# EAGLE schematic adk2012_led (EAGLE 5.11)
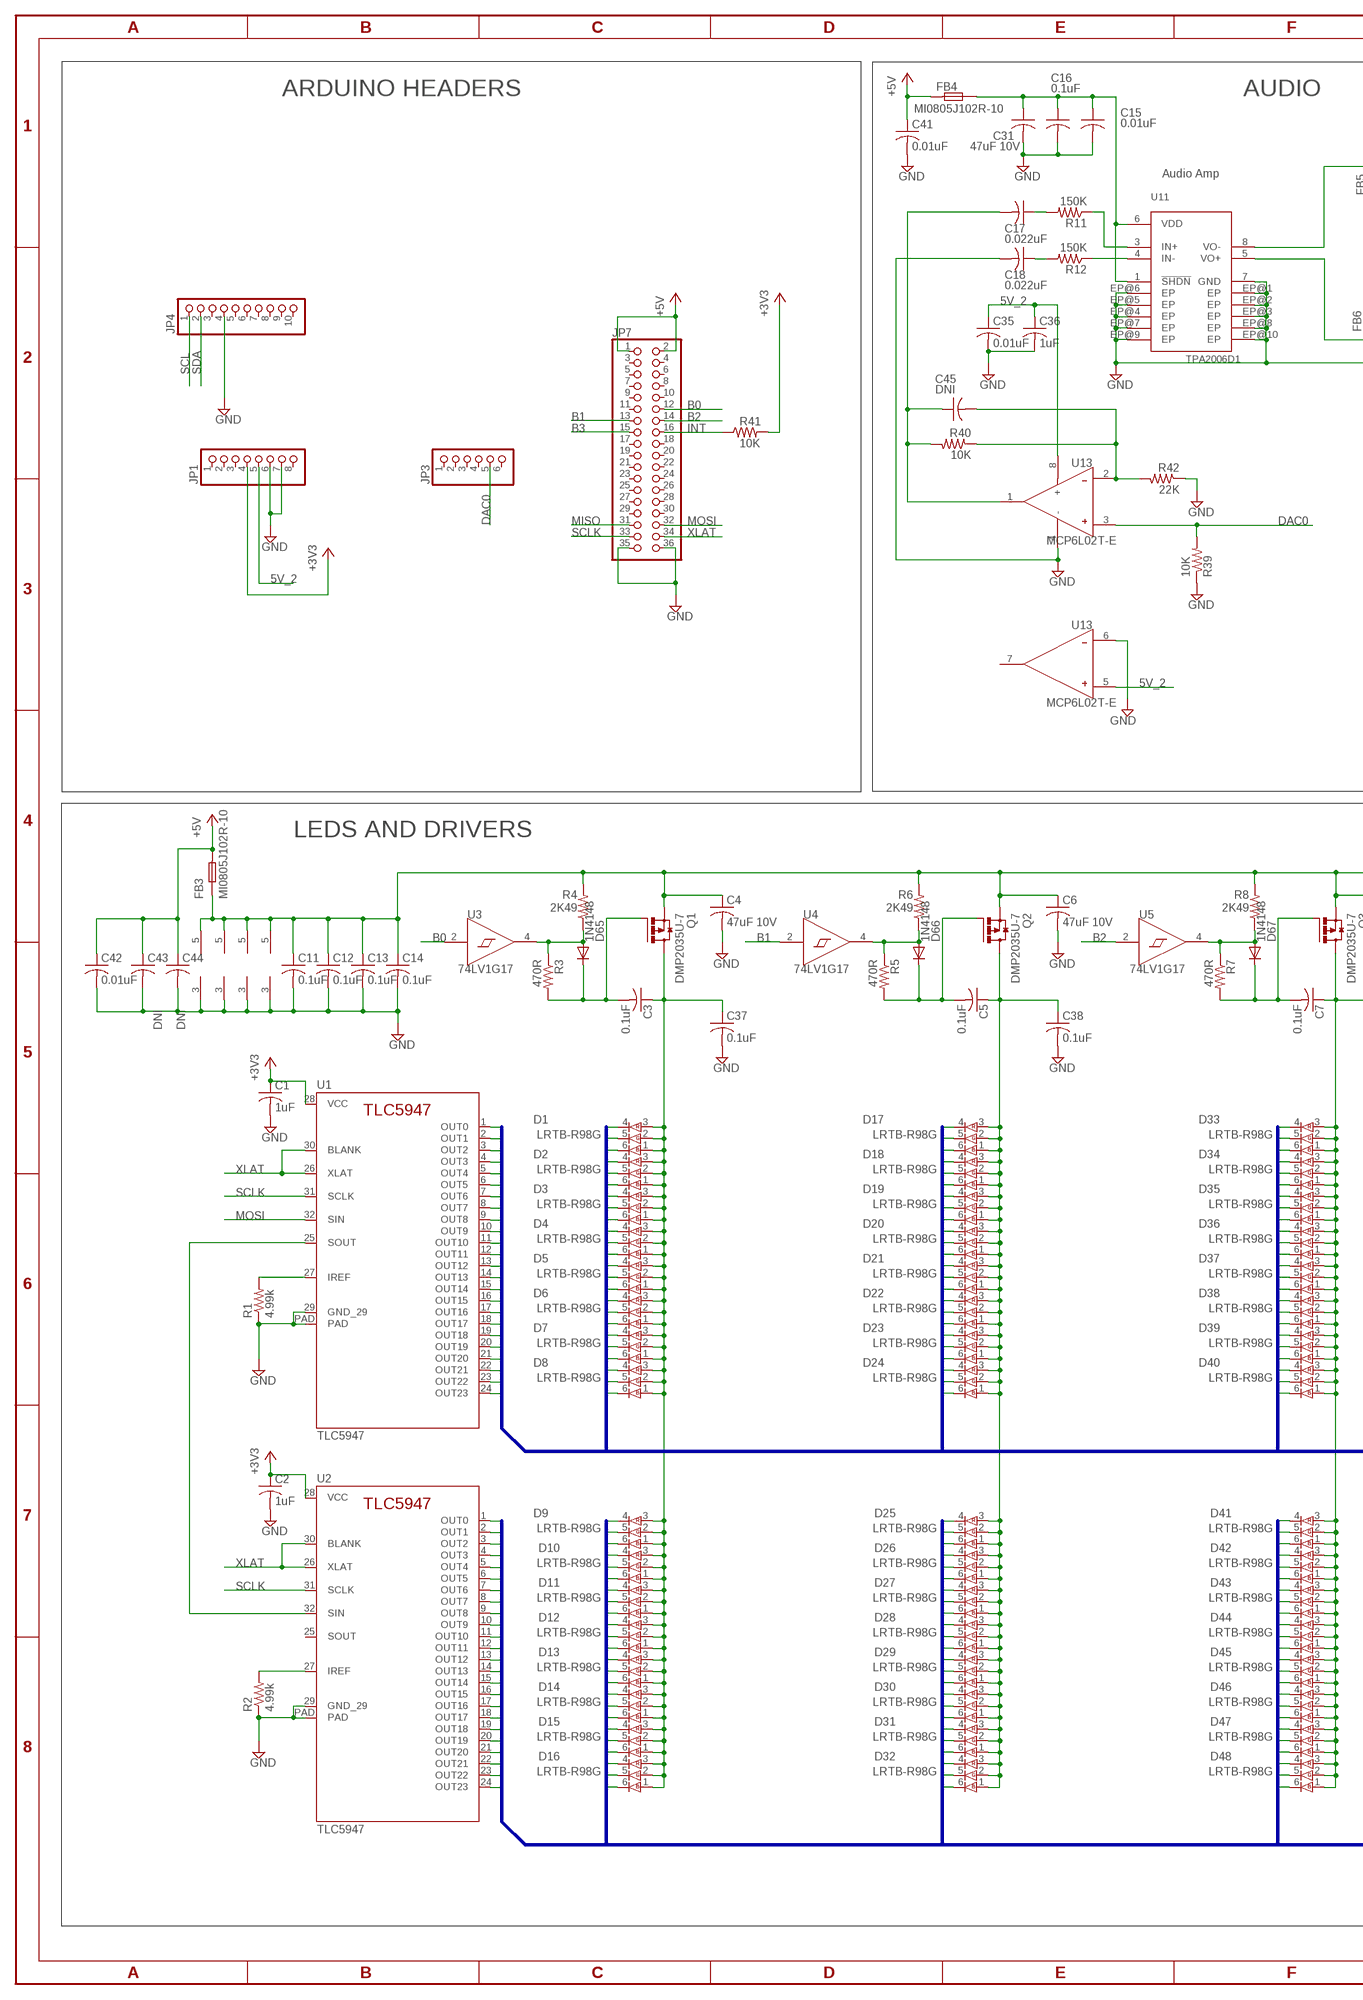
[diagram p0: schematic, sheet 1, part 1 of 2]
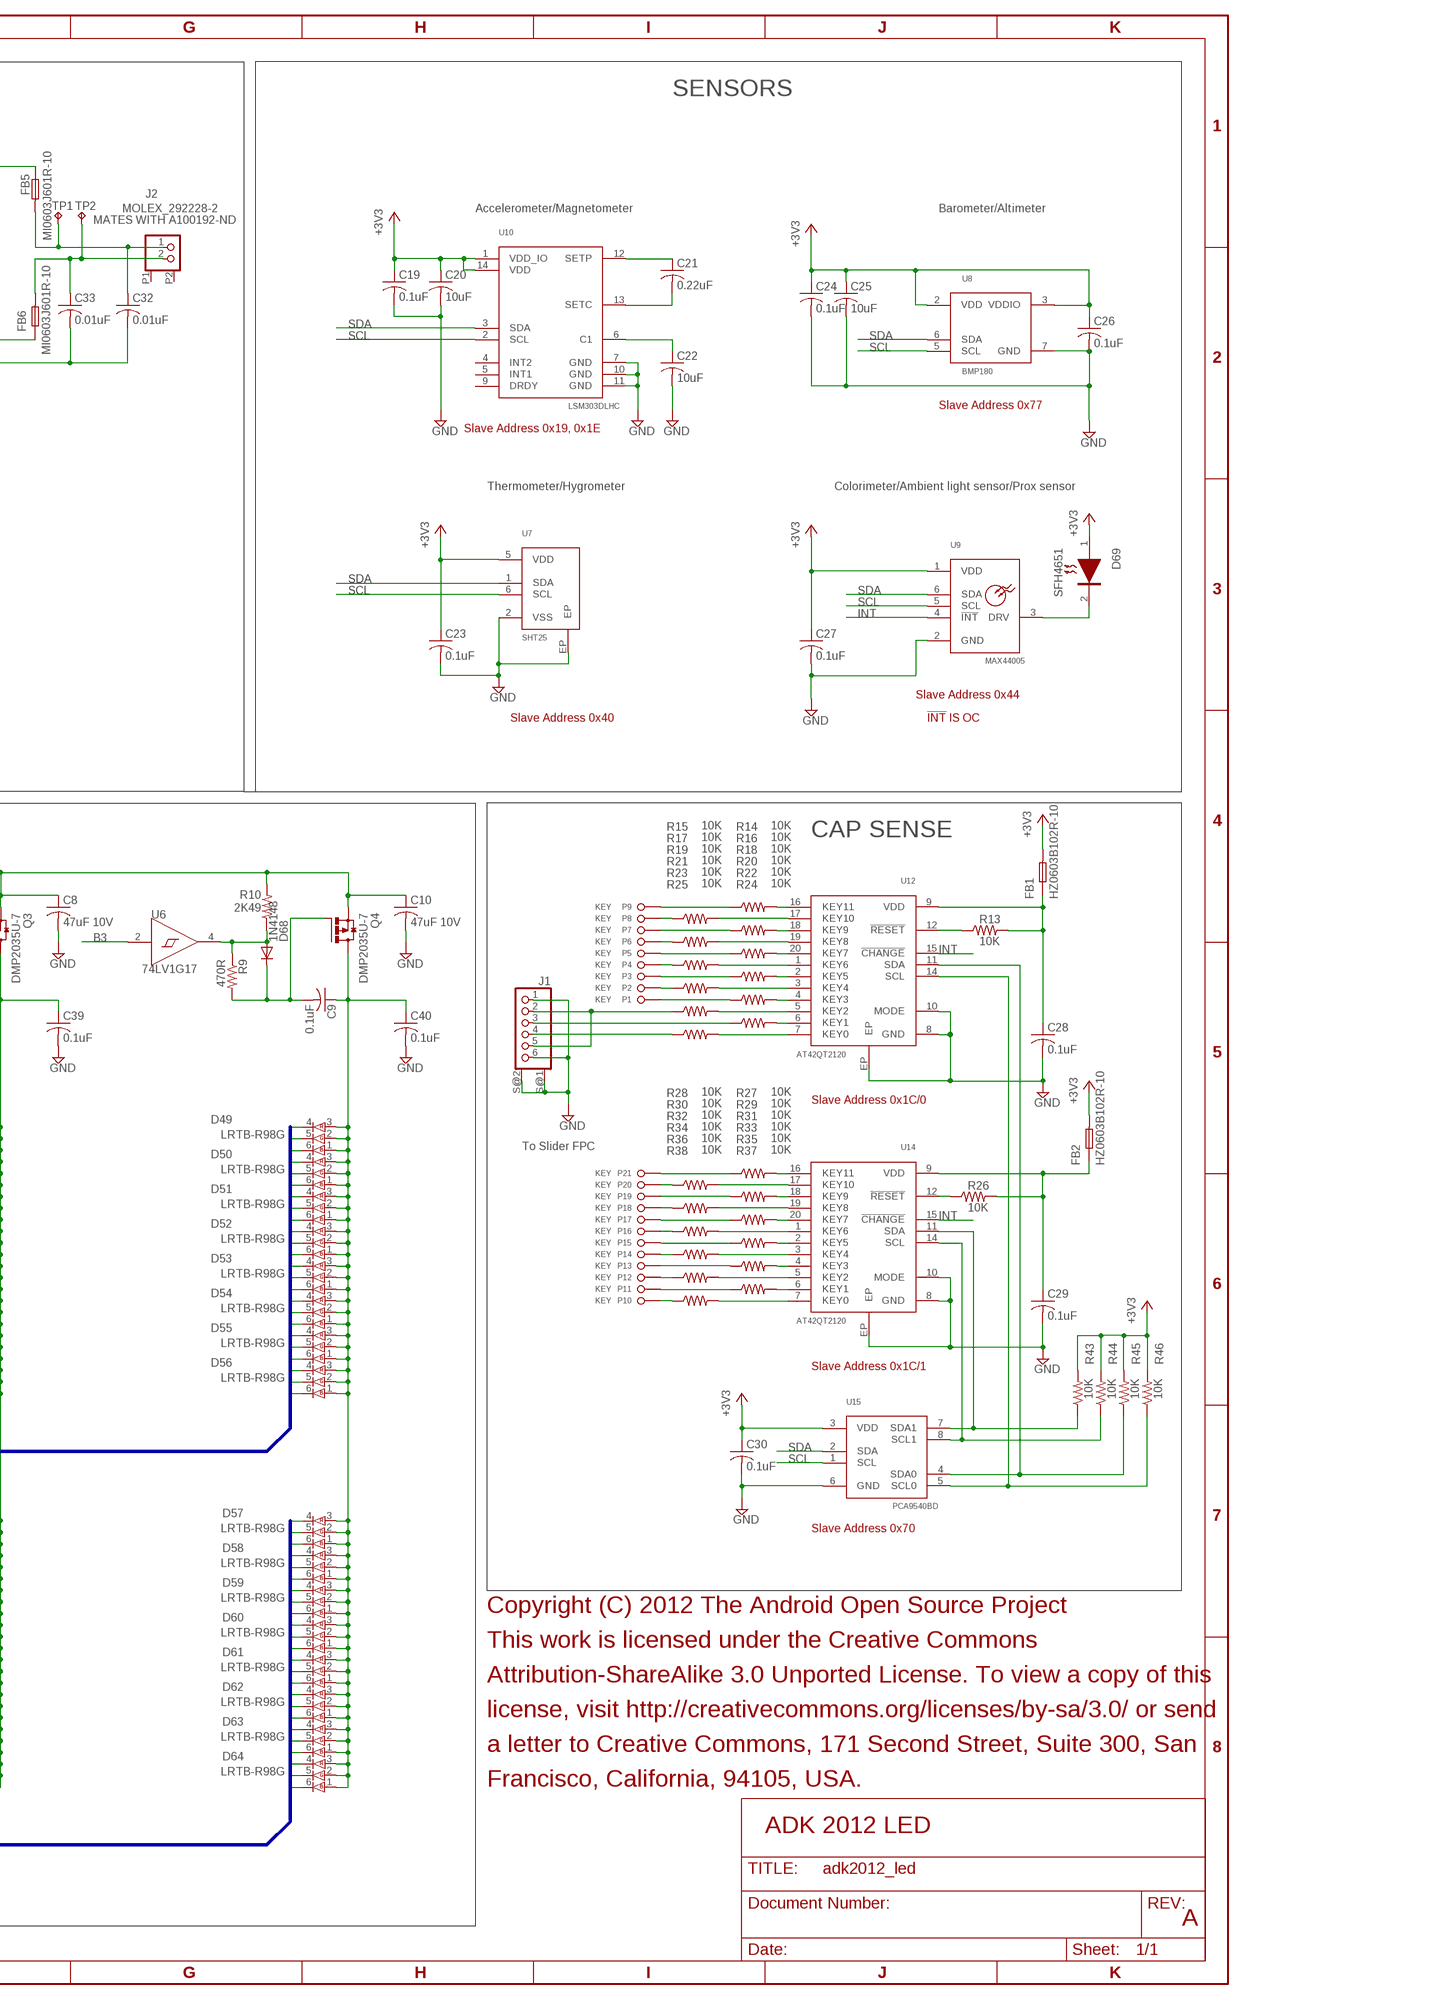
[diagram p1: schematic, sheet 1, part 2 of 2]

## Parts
C1  1uF  C-USC0603U  [C0603U]
C2  1uF  C-USC0603U  [C0603U]
C3  0.1uF  C-USC0402U  [C0402U]
C4  47uF 10V  C-USC1210U  [C1210U]
C5  0.1uF  C-USC0402U  [C0402U]
C6  47uF 10V  C-USC1210U  [C1210U]
C7  0.1uF  C-USC0402U  [C0402U]
C8  47uF 10V  C-USC1210U  [C1210U]
C9  0.1uF  C-USC0402U  [C0402U]
C10  47uF 10V  C-USC1210U  [C1210U]
C11  0.1uF  C-USC0402U  [C0402U]
C12  0.1uF  C-USC0402U  [C0402U]
C13  0.1uF  C-USC0402U  [C0402U]
C14  0.1uF  C-USC0402U  [C0402U]
C15  0.01uF  C-USC0402U  [C0402U]
C16  0.1uF  C-USC0402U  [C0402U]
C17  0.022uF  C-USC0603U  [C0603U]
C18  0.022uF  C-USC0603U  [C0603U]
C19  0.1uF  C-USC0402U  [C0402U]
C20  10uF  C-USC0603U  [C0603U]
C21  0.22uF  C-USC0603U  [C0603U]
C22  10uF  C-USC0603U  [C0603U]
C23  0.1uF  C-USC0402U  [C0402U]
C24  0.1uF  C-USC0402U  [C0402U]
C25  10uF  C-USC0603U  [C0603U]
C26  0.1uF  C-USC0402U  [C0402U]
C27  0.1uF  C-USC0402U  [C0402U]
C28  0.1uF  C-USC0402U  [C0402U]
C29  0.1uF  C-USC0402U  [C0402U]
C30  0.1uF  C-USC0402U  [C0402U]
C31  47uF 10V  C-USC1210U  [C1210U]
C32  0.01uF  C-USC0402U  [C0402U]
C33  0.01uF  C-USC0402U  [C0402U]
C35  0.01uF  C-USC0402U  [C0402U]
C36  1uF  C-USC0603U  [C0603U]
C37  0.1uF  C-USC0402U  [C0402U]
C38  0.1uF  C-USC0402U  [C0402U]
C39  0.1uF  C-USC0402U  [C0402U]
C40  0.1uF  C-USC0402U  [C0402U]
C41  0.01uF  C-USC0402U  [C0402U]
C42  0.01uF  C-USC0402U  [C0402U]
C43  DNI  C-USC1210U  [C1210U]
C44  DNI  C-USC1210U  [C1210U]
C45  DNI  C-USC0402U  [C0402U]
D1  LRTB-R98G  [LRTB-98G]
D2  LRTB-R98G  [LRTB-98G]
D3  LRTB-R98G  [LRTB-98G]
D4  LRTB-R98G  [LRTB-98G]
D5  LRTB-R98G  [LRTB-98G]
D6  LRTB-R98G  [LRTB-98G]
D7  LRTB-R98G  [LRTB-98G]
D8  LRTB-R98G  [LRTB-98G]
D9  LRTB-R98G  [LRTB-98G]
D10  LRTB-R98G  [LRTB-98G]
D11  LRTB-R98G  [LRTB-98G]
D12  LRTB-R98G  [LRTB-98G]
D13  LRTB-R98G  [LRTB-98G]
D14  LRTB-R98G  [LRTB-98G]
D15  LRTB-R98G  [LRTB-98G]
D16  LRTB-R98G  [LRTB-98G]
D17  LRTB-R98G  [LRTB-98G]
D18  LRTB-R98G  [LRTB-98G]
D19  LRTB-R98G  [LRTB-98G]
D20  LRTB-R98G  [LRTB-98G]
D21  LRTB-R98G  [LRTB-98G]
D22  LRTB-R98G  [LRTB-98G]
D23  LRTB-R98G  [LRTB-98G]
D24  LRTB-R98G  [LRTB-98G]
D25  LRTB-R98G  [LRTB-98G]
D26  LRTB-R98G  [LRTB-98G]
D27  LRTB-R98G  [LRTB-98G]
D28  LRTB-R98G  [LRTB-98G]
D29  LRTB-R98G  [LRTB-98G]
D30  LRTB-R98G  [LRTB-98G]
D31  LRTB-R98G  [LRTB-98G]
D32  LRTB-R98G  [LRTB-98G]
D33  LRTB-R98G  [LRTB-98G]
D34  LRTB-R98G  [LRTB-98G]
D35  LRTB-R98G  [LRTB-98G]
D36  LRTB-R98G  [LRTB-98G]
D37  LRTB-R98G  [LRTB-98G]
D38  LRTB-R98G  [LRTB-98G]
D39  LRTB-R98G  [LRTB-98G]
D40  LRTB-R98G  [LRTB-98G]
D41  LRTB-R98G  [LRTB-98G]
D42  LRTB-R98G  [LRTB-98G]
D43  LRTB-R98G  [LRTB-98G]
D44  LRTB-R98G  [LRTB-98G]
D45  LRTB-R98G  [LRTB-98G]
D46  LRTB-R98G  [LRTB-98G]
D47  LRTB-R98G  [LRTB-98G]
D48  LRTB-R98G  [LRTB-98G]
D49  LRTB-R98G  [LRTB-98G]
D50  LRTB-R98G  [LRTB-98G]
D51  LRTB-R98G  [LRTB-98G]
D52  LRTB-R98G  [LRTB-98G]
D53  LRTB-R98G  [LRTB-98G]
D54  LRTB-R98G  [LRTB-98G]
D55  LRTB-R98G  [LRTB-98G]
D56  LRTB-R98G  [LRTB-98G]
D57  LRTB-R98G  [LRTB-98G]
D58  LRTB-R98G  [LRTB-98G]
D59  LRTB-R98G  [LRTB-98G]
D60  LRTB-R98G  [LRTB-98G]
D61  LRTB-R98G  [LRTB-98G]
D62  LRTB-R98G  [LRTB-98G]
D63  LRTB-R98G  [LRTB-98G]
D64  LRTB-R98G  [LRTB-98G]
D65  1N4148  DIODE-SOD323-R  [SOD323-R]
D66  1N4148  DIODE-SOD323-R  [SOD323-R]
D67  1N4148  DIODE-SOD323-R  [SOD323-R]
D68  1N4148  DIODE-SOD323-R  [SOD323-R]
D69  SFH4651  [SFH4651]
FB1  HZ0603B102R-10  FERRITE0603  [FB0603]
FB2  HZ0603B102R-10  FERRITE0603  [FB0603]
FB3  MI0805J102R-10  FERRITE0805  [FB0805]
FB4  MI0805J102R-10  FERRITE0805  [FB0805]
FB5  MI0603J601R-10  FERRITE0603  [FB0603]
FB6  MI0603J601R-10  FERRITE0603  [FB0603]
J1  FCI_HFW6R-2ST  [FCI_HFW6R-2ST]
J2  MOLEX_292228-2  [MOLEX_292228-2]
JP1  SULLINS_GEC08SABN  [SULLINS_GEC08SABN]
JP3  SULLINS_GEC06SABN  [SULLINS_GEC06SABN]
JP4  SULLINS_GEC10SABN  [SULLINS_GEC10SABN]
JP7  SULLINS_GEC18DABN  [SULLINS_GEC18DABN]
P1  KEY  CAP_SENSE1  [CAP_SENSE1]
P2  KEY  CAP_SENSE1  [CAP_SENSE1]
P3  KEY  CAP_SENSE1  [CAP_SENSE1]
P4  KEY  CAP_SENSE1  [CAP_SENSE1]
P5  KEY  CAP_SENSE1  [CAP_SENSE1]
P6  KEY  CAP_SENSE1  [CAP_SENSE1]
P7  KEY  CAP_SENSE1  [CAP_SENSE1]
P8  KEY  CAP_SENSE1  [CAP_SENSE1]
P9  KEY  CAP_SENSE1  [CAP_SENSE1]
P10  KEY  CAP_SENSE1  [CAP_SENSE1]
P11  KEY  CAP_SENSE1  [CAP_SENSE1]
P12  KEY  CAP_SENSE1  [CAP_SENSE1]
P13  KEY  CAP_SENSE1  [CAP_SENSE1]
P14  KEY  CAP_SENSE1  [CAP_SENSE1]
P15  KEY  CAP_SENSE1  [CAP_SENSE1]
P16  KEY  CAP_SENSE1  [CAP_SENSE1]
P17  KEY  CAP_SENSE1  [CAP_SENSE1]
P18  KEY  CAP_SENSE1  [CAP_SENSE1]
P19  KEY  CAP_SENSE1  [CAP_SENSE1]
P20  KEY  CAP_SENSE1  [CAP_SENSE1]
P21  KEY  CAP_SENSE1  [CAP_SENSE1]
Q1  DMP2035U-7  FDN360P  [SUPER-SOT3]
Q2  DMP2035U-7  FDN360P  [SUPER-SOT3]
Q3  DMP2035U-7  FDN360P  [SUPER-SOT3]
Q4  DMP2035U-7  FDN360P  [SUPER-SOT3]
R1  4.99k  R-US_R0603U  [R0603U]
R2  4.99k  R-US_R0603U  [R0603U]
R3  470R  R-US_R0603U  [R0603U]
R4  2K49  R-US_R0603U  [R0603U]
R5  470R  R-US_R0603U  [R0603U]
R6  2K49  R-US_R0603U  [R0603U]
R7  470R  R-US_R0603U  [R0603U]
R8  2K49  R-US_R0603U  [R0603U]
R9  470R  R-US_R0603U  [R0603U]
R10  2K49  R-US_R0603U  [R0603U]
R11  150K  R-US_R0603U  [R0603U]
R12  150K  R-US_R0603U  [R0603U]
R13  10K  R-US_R0402U  [R0402U]
R14  10K  R-US_R0402U  [R0402U]
R15  10K  R-US_R0402U  [R0402U]
R16  10K  R-US_R0402U  [R0402U]
R17  10K  R-US_R0402U  [R0402U]
R18  10K  R-US_R0402U  [R0402U]
R19  10K  R-US_R0402U  [R0402U]
R20  10K  R-US_R0402U  [R0402U]
R21  10K  R-US_R0402U  [R0402U]
R22  10K  R-US_R0402U  [R0402U]
R23  10K  R-US_R0402U  [R0402U]
R24  10K  R-US_R0402U  [R0402U]
R25  10K  R-US_R0402U  [R0402U]
R26  10K  R-US_R0402U  [R0402U]
R27  10K  R-US_R0402U  [R0402U]
R28  10K  R-US_R0402U  [R0402U]
R29  10K  R-US_R0402U  [R0402U]
R30  10K  R-US_R0402U  [R0402U]
R31  10K  R-US_R0402U  [R0402U]
R32  10K  R-US_R0402U  [R0402U]
R33  10K  R-US_R0402U  [R0402U]
R34  10K  R-US_R0402U  [R0402U]
R35  10K  R-US_R0402U  [R0402U]
R36  10K  R-US_R0402U  [R0402U]
R37  10K  R-US_R0402U  [R0402U]
R38  10K  R-US_R0402U  [R0402U]
R39  10K  R-US_R0603U  [R0603U]
R40  10K  R-US_R0603U  [R0603U]
R41  10K  R-US_R0603U  [R0603U]
R42  22K  R-US_R0603U  [R0603U]
R43  10K  R-US_R0402U  [R0402U]
R44  10K  R-US_R0402U  [R0402U]
R45  10K  R-US_R0402U  [R0402U]
R46  10K  R-US_R0402U  [R0402U]
TP1  TPTP10R  [TP10R]
TP2  TPTP10R  [TP10R]
U1  TLC5947  [QFN32-RHB]
U2  TLC5947  [QFN32-RHB]
U3  74LV1G17  [SOT-553]
U4  74LV1G17  [SOT-553]
U5  74LV1G17  [SOT-553]
U6  74LV1G17  [SOT-553]
U7  SHT25  [SHT25]
U8  BMP180  [BMP180]
U9  MAX44005  MAX_OPTO  [OTDFN-6]
U10  LSM303DLHC  [LGA35-14]
U11  TPA2006D1  [DFN3030-8]
U12  AT42QT2120  [VQFN3030-20]
U13  MCP6L02T-E  OPAMP_DUAL  [SO-8]
U14  AT42QT2120  [VQFN3030-20]
U15  PCA9540BD  [SO-8]

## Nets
5V_2: C35.1 C36.1 JP1.5 U13.5(P) U13.8(+)
+3V3: C1.1 C2.1 C19.1 C20.1 C23.1 C24.1 C25.1 C26.1 C27.1 C30.1 D69.1(A) FB1.2 FB2.2 JP1.4 R41.2 R43.2 R44.2 R45.2 R46.2 U1.28(VCC) U2.28(VCC) U7.5(VDD) U8.2(VDD) U8.3(VDDIO) U9.1(VDD) U10.1(VDD_IO) U10.14(VDD) U15.3(VDD)
+5V: C41.1 C42.1 C43.1 C44.1 FB3.2 FB4.2 JP7.1 JP7.2
B0: JP7.12 U3.2(A)
B1: JP7.13 U4.2(A)
B2: JP7.14 U5.2(A)
B3: JP7.15 U6.2(A)
BANK0-: D65.A R3.1 R4.1 U3.4(Y)
BANK1-: D66.A R5.1 R6.1 U4.4(Y)
BANK2-: D67.A R7.1 R8.1 U5.4(Y)
BANK2-1: D68.A R9.1 R10.1 U6.4(Y)
DAC0: JP3.5 R39.2 U13.3(P)
DRVA0: D1.4(RK) D17.4(RK) D33.4(RK) D49.4(RK) U1.1(OUT0)
DRVA1: D1.5(GK) D17.5(GK) D33.5(GK) D49.5(GK) U1.2(OUT1)
DRVA2: D1.6(BK) D17.6(BK) D33.6(BK) D49.6(BK) U1.3(OUT2)
DRVA3: D2.4(RK) D18.4(RK) D34.4(RK) D50.4(RK) U1.4(OUT3)
DRVA4: D2.5(GK) D18.5(GK) D34.5(GK) D50.5(GK) U1.5(OUT4)
DRVA5: D2.6(BK) D18.6(BK) D34.6(BK) D50.6(BK) U1.6(OUT5)
DRVA6: D3.4(RK) D19.4(RK) D35.4(RK) D51.4(RK) U1.7(OUT6)
DRVA7: D3.5(GK) D19.5(GK) D35.5(GK) D51.5(GK) U1.8(OUT7)
DRVA8: D3.6(BK) D19.6(BK) D35.6(BK) D51.6(BK) U1.9(OUT8)
DRVA9: D4.4(RK) D20.4(RK) D36.4(RK) D52.4(RK) U1.10(OUT9)
DRVA10: D4.5(GK) D20.5(GK) D36.5(GK) D52.5(GK) U1.11(OUT10)
DRVA11: D4.6(BK) D20.6(BK) D36.6(BK) D52.6(BK) U1.12(OUT11)
DRVA12: D5.4(RK) D21.4(RK) D37.4(RK) D53.4(RK) U1.13(OUT12)
DRVA13: D5.5(GK) D21.5(GK) D37.5(GK) D53.5(GK) U1.14(OUT13)
DRVA14: D5.6(BK) D21.6(BK) D37.6(BK) D53.6(BK) U1.15(OUT14)
DRVA15: D6.4(RK) D22.4(RK) D38.4(RK) D54.4(RK) U1.16(OUT15)
DRVA16: D6.5(GK) D22.5(GK) D38.5(GK) D54.5(GK) U1.17(OUT16)
DRVA17: D6.6(BK) D22.6(BK) D38.6(BK) D54.6(BK) U1.18(OUT17)
DRVA18: D7.4(RK) D23.4(RK) D39.4(RK) D55.4(RK) U1.19(OUT18)
DRVA19: D7.5(GK) D23.5(GK) D39.5(GK) D55.5(GK) U1.20(OUT19)
DRVA20: D7.6(BK) D23.6(BK) D39.6(BK) D55.6(BK) U1.21(OUT20)
DRVA21: D8.4(RK) D24.4(RK) D40.4(RK) D56.4(RK) U1.22(OUT21)
DRVA22: D8.5(GK) D24.5(GK) D40.5(GK) D56.5(GK) U1.23(OUT22)
DRVA23: D8.6(BK) D24.6(BK) D40.6(BK) D56.6(BK) U1.24(OUT23)
DRVB0: D9.4(RK) D25.4(RK) D41.4(RK) D57.4(RK) U2.1(OUT0)
DRVB1: D9.5(GK) D25.5(GK) D41.5(GK) D57.5(GK) U2.2(OUT1)
DRVB2: D9.6(BK) D25.6(BK) D41.6(BK) D57.6(BK) U2.3(OUT2)
DRVB3: D10.4(RK) D26.4(RK) D42.4(RK) D58.4(RK) U2.4(OUT3)
DRVB4: D10.5(GK) D26.5(GK) D42.5(GK) D58.5(GK) U2.5(OUT4)
DRVB5: D10.6(BK) D26.6(BK) D42.6(BK) D58.6(BK) U2.6(OUT5)
DRVB6: D11.4(RK) D27.4(RK) D43.4(RK) D59.4(RK) U2.7(OUT6)
DRVB7: D11.5(GK) D27.5(GK) D43.5(GK) D59.5(GK) U2.8(OUT7)
DRVB8: D11.6(BK) D27.6(BK) D43.6(BK) D59.6(BK) U2.9(OUT8)
DRVB9: D12.4(RK) D28.4(RK) D44.4(RK) D60.4(RK) U2.10(OUT9)
DRVB10: D12.5(GK) D28.5(GK) D44.5(GK) D60.5(GK) U2.11(OUT10)
DRVB11: D12.6(BK) D28.6(BK) D44.6(BK) D60.6(BK) U2.12(OUT11)
DRVB12: D13.4(RK) D29.4(RK) D45.4(RK) D61.4(RK) U2.13(OUT12)
DRVB13: D13.5(GK) D29.5(GK) D45.5(GK) D61.5(GK) U2.14(OUT13)
DRVB14: D13.6(BK) D29.6(BK) D45.6(BK) D61.6(BK) U2.15(OUT14)
DRVB15: D14.4(RK) D30.4(RK) D46.4(RK) D62.4(RK) U2.16(OUT15)
DRVB16: D14.5(GK) D30.5(GK) D46.5(GK) D62.5(GK) U2.17(OUT16)
DRVB17: D14.6(BK) D30.6(BK) D46.6(BK) D62.6(BK) U2.18(OUT17)
DRVB18: D15.4(RK) D31.4(RK) D47.4(RK) D63.4(RK) U2.19(OUT18)
DRVB19: D15.5(GK) D31.5(GK) D47.5(GK) D63.5(GK) U2.20(OUT19)
DRVB20: D15.6(BK) D31.6(BK) D47.6(BK) D63.6(BK) U2.21(OUT20)
DRVB21: D16.4(RK) D32.4(RK) D48.4(RK) D64.4(RK) U2.22(OUT21)
DRVB22: D16.5(GK) D32.5(GK) D48.5(GK) D64.5(GK) U2.23(OUT22)
DRVB23: D16.6(BK) D32.6(BK) D48.6(BK) D64.6(BK) U2.24(OUT23)
GND: C1.2 C2.2 C4.2 C6.2 C8.2 C10.2 C11.2 C12.2 C13.2 C14.2 C15.2 C16.2 C18.2 C19.2 C20.2 C22.2 C23.2 C24.2 C25.2 C26.2 C27.2 C28.2 C29.2 C30.2 C31.2 C32.2 C33.2 C35.2 C36.2 C37.2 C38.2 C39.2 C40.2 C41.2 C42.2 C43.2 C44.2 J1.1 J1.6 J1.S@1(S) J1.S@2(S) JP1.6 JP1.7 JP4.4 JP7.35 JP7.36 R1.1 R2.1 R39.1 R42.1 U1.29(GND_29) U1.PAD U2.29(GND_29) U2.PAD U3.3(GND) U4.3(GND) U5.3(GND) U6.3(GND) U7.2(VSS) U7.EP U8.7(GND) U9.2(GND) U10.7(GND) U10.10(GND) U10.11(GND) U11.7(GND) U11.EP@1(EP) U11.EP@2(EP) U11.EP@3(EP) U11.EP@4(EP) U11.EP@5(EP) U11.EP@6(EP) U11.EP@7(EP) U11.EP@8(EP) U11.EP@9(EP) U11.EP@10(EP) U12.8(GND) U12.10(MODE) U12.EP U13.4(-) U13.6(N) U14.8(GND) U14.10(MODE) U14.EP U15.6(GND)
INT: JP7.16 R41.1 U9.4(!INT) U12.15(!CHANGE) U14.15(!CHANGE)
MISO: JP7.31
MOSI: JP7.32 U1.32(SIN)
N$1: U1.25(SOUT) U2.32(SIN)
N$2: R2.2 U2.27(IREF)
N$3: C3.2 D65.C Q1.1(G) R3.2
N$5: R1.2 U1.27(IREF)
N$6: C5.2 D66.C Q2.1(G) R5.2
N$7: C7.2 D67.C Q3.1(G) R7.2
N$8: C21.1 U10.12(SETP)
N$9: C21.2 U10.13(SETC)
N$11: C22.1 U10.6(C1)
N$12: C9.2 D68.C Q4.1(G) R9.2
N$13: R11.1 U11.3(IN+)
N$14: R12.1 U11.4(IN-)
N$15: C17.1 R11.2
N$16: C18.1 R12.2
N$17: R46.1 U12.14(SCL) U15.5(SCL0)
N$18: FB5.1 U11.8(VO-)
N$19: R45.1 U12.11(SDA) U15.4(SDA0)
N$20: FB6.1 U11.5(VO+)
N$21: J1.2 J1.5 R23.1
N$22: J1.3 R24.1
N$23: C28.1 FB1.1 R13.2 U12.9(VDD)
N$24: D69.2(K) U9.3(DRV)
N$25: J1.4 R25.1
N$26: R13.1 U12.12(!RESET)
N$27: C29.1 FB2.1 R26.2 U14.9(VDD)
N$28: R23.2 U12.5(KEY2)
N$29: R25.2 U12.7(KEY0)
N$30: R24.2 U12.6(KEY1)
N$32: C33.1 FB6.2 J2.2 TP2.TP
N$33: R26.1 U14.12(!RESET)
N$34: R44.1 U14.14(SCL) U15.8(SCL1)
N$35: R43.1 U14.11(SDA) U15.7(SDA1)
N$36: R22.2 U12.4(KEY3)
N$37: P1.P$1 R22.1
N$38: P2.P$1 R21.1
N$39: R21.2 U12.3(KEY4)
N$40: R20.2 U12.2(KEY5)
N$41: R14.2 U12.16(KEY11)
N$42: P12.P$1 R36.1
N$43: R27.2 U14.16(KEY11)
N$44: P21.P$1 R27.1
N$45: R36.2 U14.5(KEY2)
N$46: P11.P$1 R37.1
N$47: P10.P$1 R38.1
N$48: R38.2 U14.7(KEY0)
N$49: R37.2 U14.6(KEY1)
N$50: R35.2 U14.4(KEY3)
N$51: P13.P$1 R35.1
N$52: P14.P$1 R34.1
N$53: R34.2 U14.3(KEY4)
N$54: P9.P$1 R14.1
N$55: R19.2 U12.1(KEY6)
N$56: R18.2 U12.20(KEY7)
N$57: R17.2 U12.19(KEY8)
N$58: P7.P$1 R16.1
N$59: P6.P$1 R17.1
N$60: P5.P$1 R18.1
N$61: P4.P$1 R19.1
N$62: P3.P$1 R20.1
N$63: R16.2 U12.18(KEY9)
N$64: R15.2 U12.17(KEY10)
N$65: P8.P$1 R15.1
N$66: R33.2 U14.2(KEY5)
N$67: R32.2 U14.1(KEY6)
N$68: R31.2 U14.20(KEY7)
N$69: R30.2 U14.19(KEY8)
N$70: P19.P$1 R29.1
N$71: P18.P$1 R30.1
N$72: P17.P$1 R31.1
N$73: P16.P$1 R32.1
N$74: P15.P$1 R33.1
N$75: R29.2 U14.18(KEY9)
N$76: R28.2 U14.17(KEY10)
N$77: P20.P$1 R28.1
N$78: C4.1 C6.1 C8.1 C10.1 C11.1 C12.1 C13.1 C14.1 FB3.1 Q1.2(S) Q2.2(S) Q3.2(S) Q4.2(S) R4.2 R6.2 R8.2 R10.2 U3.5(VCC) U4.5(VCC) U5.5(VCC) U6.5(VCC)
N$79: C32.1 FB5.2 J2.1 TP1.TP
N$80: C15.1 C16.1 C31.1 FB4.1 U11.1(!SHDN) U11.6(VDD)
N$82: C17.2 C45.1 R40.2 U13.1(OUT)
N$83: C45.2 R40.1 R42.2 U13.2(N)
SCL: JP4.1 U7.6(SCL) U8.5(SCL) U9.5(SCL) U10.2(SCL) U15.1(SCL)
SCLK: JP7.33 U1.31(SCLK) U2.31(SCLK)
SDA: JP4.2 U7.1(SDA) U8.6(SDA) U9.6(SDA) U10.3(SDA) U15.2(SDA)
VLED_BANK0: C3.1 C37.1 D1.1(BA) D1.2(GA) D1.3(RA) D2.1(BA) D2.2(GA) D2.3(RA) D3.1(BA) D3.2(GA) D3.3(RA) D4.1(BA) D4.2(GA) D4.3(RA) D5.1(BA) D5.2(GA) D5.3(RA) D6.1(BA) D6.2(GA) D6.3(RA) D7.1(BA) D7.2(GA) D7.3(RA) D8.1(BA) D8.2(GA) D8.3(RA) D9.1(BA) D9.2(GA) D9.3(RA) D10.1(BA) D10.2(GA) D10.3(RA) D11.1(BA) D11.2(GA) D11.3(RA) D12.1(BA) D12.2(GA) D12.3(RA) D13.1(BA) D13.2(GA) D13.3(RA) D14.1(BA) D14.2(GA) D14.3(RA) D15.1(BA) D15.2(GA) D15.3(RA) D16.1(BA) D16.2(GA) D16.3(RA) Q1.3(D)
VLED_BANK1: C5.1 C38.1 D17.1(BA) D17.2(GA) D17.3(RA) D18.1(BA) D18.2(GA) D18.3(RA) D19.1(BA) D19.2(GA) D19.3(RA) D20.1(BA) D20.2(GA) D20.3(RA) D21.1(BA) D21.2(GA) D21.3(RA) D22.1(BA) D22.2(GA) D22.3(RA) D23.1(BA) D23.2(GA) D23.3(RA) D24.1(BA) D24.2(GA) D24.3(RA) D25.1(BA) D25.2(GA) D25.3(RA) D26.1(BA) D26.2(GA) D26.3(RA) D27.1(BA) D27.2(GA) D27.3(RA) D28.1(BA) D28.2(GA) D28.3(RA) D29.1(BA) D29.2(GA) D29.3(RA) D30.1(BA) D30.2(GA) D30.3(RA) D31.1(BA) D31.2(GA) D31.3(RA) D32.1(BA) D32.2(GA) D32.3(RA) Q2.3(D)
VLED_BANK2: C7.1 C39.1 D33.1(BA) D33.2(GA) D33.3(RA) D34.1(BA) D34.2(GA) D34.3(RA) D35.1(BA) D35.2(GA) D35.3(RA) D36.1(BA) D36.2(GA) D36.3(RA) D37.1(BA) D37.2(GA) D37.3(RA) D38.1(BA) D38.2(GA) D38.3(RA) D39.1(BA) D39.2(GA) D39.3(RA) D40.1(BA) D40.2(GA) D40.3(RA) D41.1(BA) D41.2(GA) D41.3(RA) D42.1(BA) D42.2(GA) D42.3(RA) D43.1(BA) D43.2(GA) D43.3(RA) D44.1(BA) D44.2(GA) D44.3(RA) D45.1(BA) D45.2(GA) D45.3(RA) D46.1(BA) D46.2(GA) D46.3(RA) D47.1(BA) D47.2(GA) D47.3(RA) D48.1(BA) D48.2(GA) D48.3(RA) Q3.3(D)
VLED_BANK3: C9.1 C40.1 D49.1(BA) D49.2(GA) D49.3(RA) D50.1(BA) D50.2(GA) D50.3(RA) D51.1(BA) D51.2(GA) D51.3(RA) D52.1(BA) D52.2(GA) D52.3(RA) D53.1(BA) D53.2(GA) D53.3(RA) D54.1(BA) D54.2(GA) D54.3(RA) D55.1(BA) D55.2(GA) D55.3(RA) D56.1(BA) D56.2(GA) D56.3(RA) D57.1(BA) D57.2(GA) D57.3(RA) D58.1(BA) D58.2(GA) D58.3(RA) D59.1(BA) D59.2(GA) D59.3(RA) D60.1(BA) D60.2(GA) D60.3(RA) D61.1(BA) D61.2(GA) D61.3(RA) D62.1(BA) D62.2(GA) D62.3(RA) D63.1(BA) D63.2(GA) D63.3(RA) D64.1(BA) D64.2(GA) D64.3(RA) Q4.3(D)
XLAT: JP7.34 U1.26(XLAT) U1.30(BLANK) U2.26(XLAT) U2.30(BLANK)
Unconnected: J2.P1(S) J2.P2(S) JP1.1 JP1.2 JP1.3 JP1.8 JP3.1 JP3.2 JP3.3 JP3.4 JP3.6 JP4.3 JP4.5 JP4.6 JP4.7 JP4.8 JP4.9 JP4.10 JP7.3 JP7.4 JP7.5 JP7.6 JP7.7 JP7.8 JP7.9 JP7.10 JP7.11 JP7.17 JP7.18 JP7.19 JP7.20 JP7.21 JP7.22 JP7.23 JP7.24 JP7.25 JP7.26 JP7.27 JP7.28 JP7.29 JP7.30 U2.25(SOUT) U10.4(INT2) U10.5(INT1) U10.9(DRDY) U13.7(OUT)

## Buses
DRVA[0..23]
DRVB[0..23]

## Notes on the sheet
- ARDUINO HEADERS | AUDIO | SENSORS
- Audio Amp
- Accelerometer/Magnetometer | Barometer/Altimeter
- MATES WITH A100192-ND
- Slave Address 0x77
- Slave Address 0x19, 0x1E
- Thermometer/Hygrometer | Colorimeter/Ambient light sensor/Prox sensor
- Slave Address 0x44
- Slave Address 0x40 | !INT! IS OC
- LEDS AND DRIVERS | CAP SENSE
- Slave Address 0x1C/0
- To Slider FPC
- Slave Address 0x1C/1
- Slave Address 0x70
- Copyright (C) 2012 The Android Open Source Project
- This work is licensed under the Creative Commons
- Attribution-ShareAlike 3.0 Unported License. To view a copy of this
- license, visit http://creativecommons.org/licenses/by-sa/3.0/ or send
- a letter to Creative Commons, 171 Second Street, Suite 300, San
- Francisco, California, 94105, USA.
- ADK 2012 LED
- A

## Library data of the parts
C1-C33 C35-C45 = rcl:C-US: CAPACITOR, American symbol
D1-D64 = adk2:LRTB-R98G
D65-D68 = diode:DIODE-: DIODE
D69 = adk2:SFH4651: Osram IR Led SFH 4651
FB1-FB6 = adk2:FERRITE: Ferrite bead
J1 = con-misc:FCI_HFW6R-2ST: FCI connector, FPC, top side contacts
J2 = con-misc:MOLEX_292228-2: MOLEX 2-pin surface mount right angle connector
JP1 = con-misc:SULLINS_GEC08SABN: Sullins single row 8-pin header
JP3 = con-misc:SULLINS_GEC06SABN
JP4 = con-misc:SULLINS_GEC10SABN
JP7 = con-misc:SULLINS_GEC18DABN: 18x2 dual row header, surface mount
P1-P21 = adk2:CAP_SENSE1: Cap sense electrode (NO BOM)
Q1-Q4 = transistor-power:FDN360P: Single P-Channel, PowerTrench (R) MOSFET Source: http://www.fairchildsemi.com/ds/FD/FDN360P.pdf
R1-R46 = rcl:R-US_: RESISTOR, American symbol
TP1 TP2 = testpad:TP
U1 U2 = tlc5947:TLC5947: Texas Instruments 24 Channel Linear LED Driver
U3-U6 = adk2:74LV1G17
U7 = adk2:SHT25: Temperature and relative humidity sensor
U8 = adk2:BMP180: Bosch BMP180 pressure sensor/altimeter
U9 = adk2:MAX_OPTO: Maxim optical sensor device (MAX44000, MAX44005, MAX88000)
U10 = adk2:LSM303DLHC
U11 = adk2:TPA2006D1
U12 U14 = adk2:AT42QT2120: Atmel QTouch 12 button/1 slider with I2C
U13 = adk2:OPAMP_DUAL: Generic 8-pin dual op amp
U15 = adk2:PCA9540B: NXP 2-channel I2C mux

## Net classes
0 default: width 0.152 mm, drill 0.305 mm, clearance 0.152 mm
